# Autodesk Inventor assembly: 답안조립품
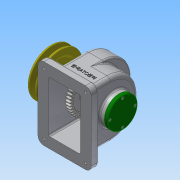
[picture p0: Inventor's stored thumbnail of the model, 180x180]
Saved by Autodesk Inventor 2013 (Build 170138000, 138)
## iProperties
Created: 2017-11
Part Number: 답안조립품
Document SubType Name: Assembly
Designer: Administrator
Author: Administrator
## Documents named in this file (14)
- C:\Users\Administrator\Desktop\471108V1030\답안조립품.iam
- C:\Users\Administrator\Desktop\471108V1030\본체.ipt
- C:\Users\Administrator\Desktop\471108V1030\V-벨트풀리.ipt
- C:\Users\Administrator\Desktop\471108V1030\뒤커버.ipt
- C:\Users\Administrator\Desktop\471108V1030\멈춤나사 - M4 x 10.ipt
- 멈춤나사 - M4 x 10.ipt
- C:\Users\Administrator\Desktop\471108V1030\베어링 6002.ipt
- C:\Users\Administrator\Desktop\471108V1030\볼트 M3 x 8.ipt
- C:\Users\Administrator\Desktop\471108V1030\스퍼기어.ipt
- C:\Users\Administrator\Desktop\471108V1030\앞커버.ipt
- C:\Users\Administrator\Desktop\471108V1030\오일 실 15 30 7.ipt
- C:\Users\Administrator\Desktop\471108V1030\축.ipt
- C:\Users\Administrator\Desktop\471108V1030\키 - 5 x 5 x 18.ipt
- C:\Users\Administrator\Desktop\471108V1030\키 - 6 x 6 x 22.ipt
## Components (1 placed, 1 different names)
1. V-벨트풀리:1
